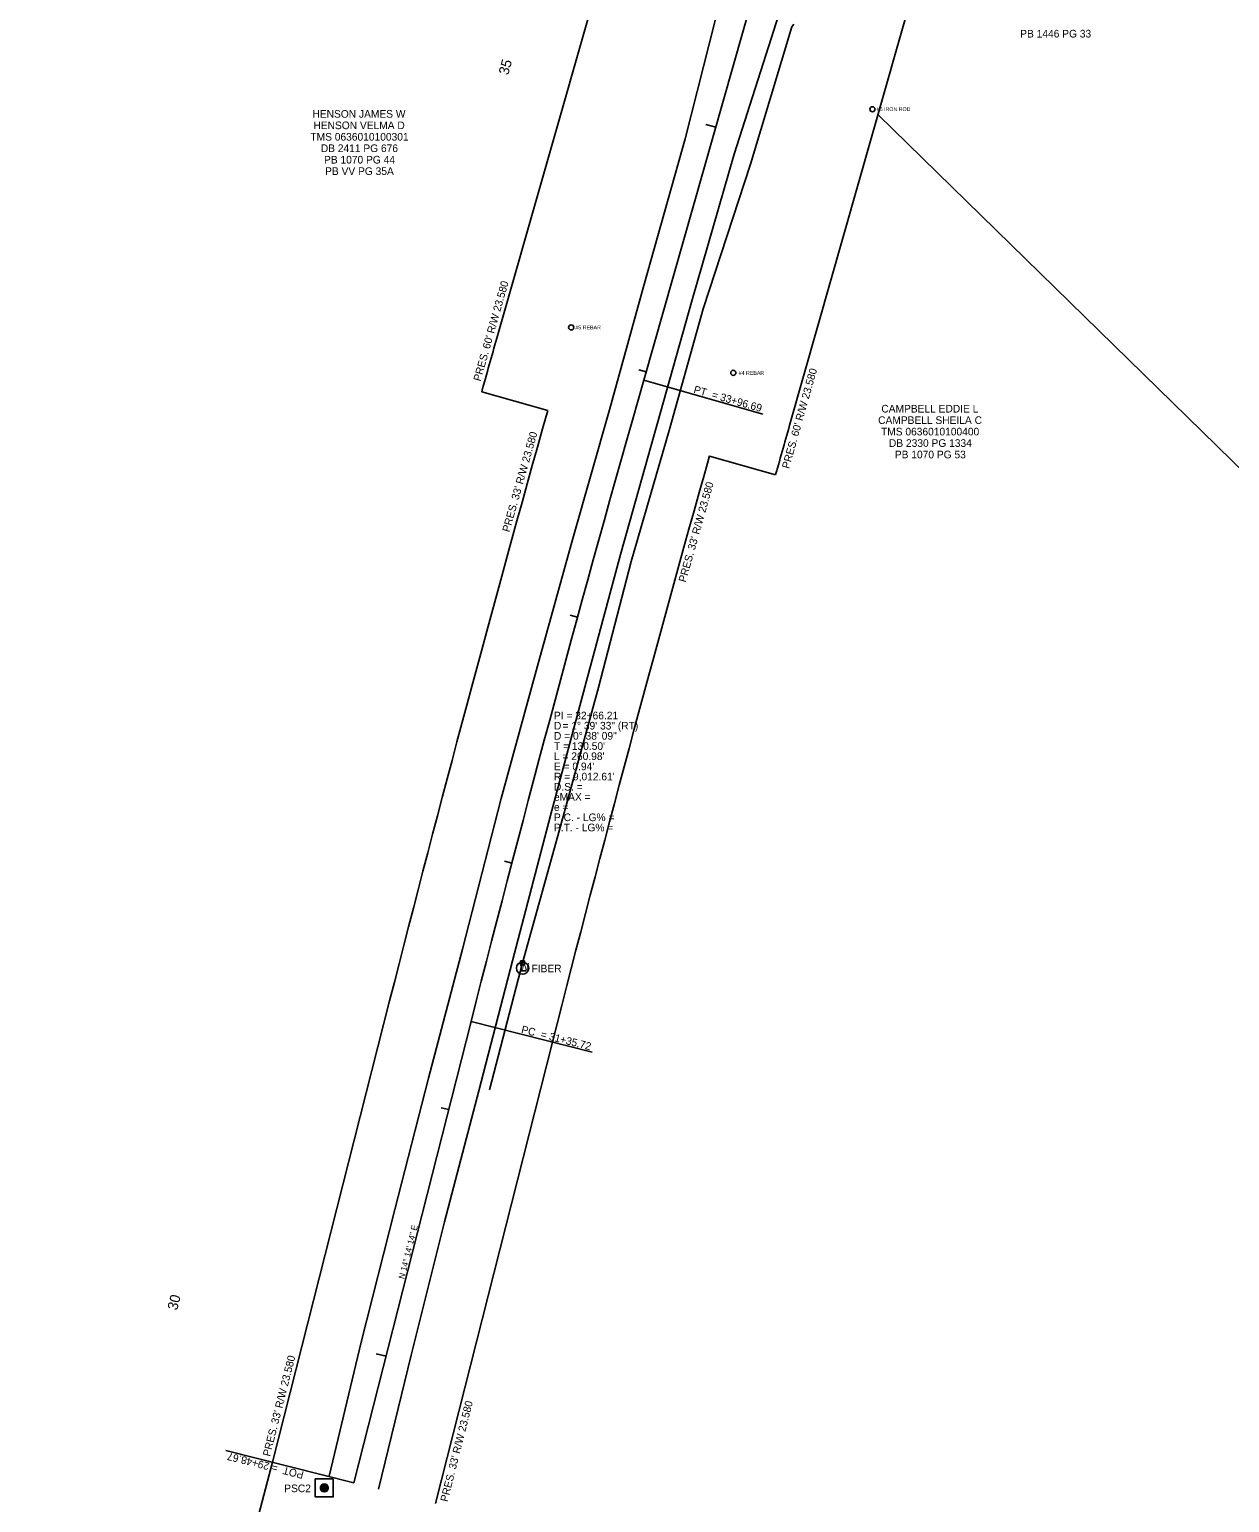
# Model space of a CAD drawing. Extents: x 1618707 to 1620612, y 1189955 to 1192629.
# Drawn here: x 1619369 to 1619840, y 1190966 to 1191545 of the extents above; entities that cross this region are included whole.
import ezdxf

# ---------------------------------------------------------------- set-up
doc = ezdxf.new("R2010")
doc.units = 0
for name, color, linetype in [('RD_EX_DV_Prop', 7, 'Continuous'), ('RD_EX_DV_Prop_txCode', 7, 'Continuous'), ('RD_EX_DV_PropPin', 7, 'Continuous'), ('RD_EX_DV_TX_Prop', 7, 'Continuous'), ('RD_EX_Road', 7, 'Continuous'), ('RD_EX_RW', 7, 'Continuous'), ('RD_EX_RW_TX', 7, 'Continuous'), ('RD_EX_SU_Telecom', 7, 'Continuous'), ('RD_EX_UT', 7, 'Continuous'), ('RD_HC_Cl', 7, 'Continuous'), ('RD_HC_Data', 7, 'Continuous'), ('RD_HC_Data_Tic', 7, 'Continuous'), ('RD_HC_Survey', 7, 'Continuous'), ('RD_HC_Survey_txCode', 7, 'Continuous'), ('RD_HC_TX_Sta20', 7, 'Continuous'), ('RD_TX_Utilities', 7, 'Continuous')]:
    doc.layers.add(name, color=color, linetype=linetype)

msp = doc.modelspace()

# ---------------------------------------------------------------- linework, layer by layer
at = {"layer": 'RD_EX_DV_Prop'}
for points in [[(1619702.33, 1191511.51), (1620061.32, 1191160.82), (1620043.47, 1191098.44), (1620079.72, 1190971.71), (1620114.14, 1190975.41), (1620199.12, 1190966.95), (1620233.68, 1190992.64), (1620266.69, 1190990.15), (1619987.51, 1189954.99)], [(1619464.43, 1190982.1), (1619428.11, 1190844.09), (1619368.9, 1190592.41)]]:
    msp.add_lwpolyline(points, dxfattribs=at)
at = {"layer": 'RD_EX_DV_PropPin'}
for centre in [(1619700.11, 1191513.68), (1619581.77, 1191427.98), (1619645.47, 1191410.14)]:
    msp.add_circle(centre, 1, dxfattribs=at)
at = {"layer": 'RD_EX_Road'}
for points in [[(1619642.43, 1191568.08), (1619638.48, 1191549.06), (1619626.5, 1191502.03), (1619610.31, 1191444.44), (1619596.77, 1191395.56), (1619582.42, 1191345.02), (1619568.38, 1191294.44), (1619554.25, 1191242.83), (1619539.08, 1191183.69), (1619525.7, 1191133.06), (1619512.41, 1191081.45), (1619499.3, 1191029.35), (1619486.66, 1190976.67)], [(1619666.44, 1191560.82), (1619645.74, 1191496.06), (1619629.32, 1191438.84), (1619615.59, 1191389.97), (1619601.08, 1191338.73), (1619587.7, 1191288.59), (1619573.66, 1191236.16), (1619558.66, 1191179.12), (1619545.49, 1191128.07), (1619532.02, 1191076.56), (1619518.85, 1191024.15), (1619506.08, 1190971.55)]]:
    msp.add_lwpolyline(points, dxfattribs=at)
at = {"layer": 'RD_EX_RW'}
for p, q in [((1619552.55, 1191423.72), (1619669.87, 1191835.65)), ((1619667.96, 1191390.85), (1619785.28, 1191802.78)), ((1619546.6, 1191402.71), (1619572.58, 1191395.38)), ((1619662.09, 1191370.12), (1619636.1, 1191377.45)), ((1619464.43, 1190982.1), (1619510.43, 1191163.4)), ((1619528.41, 1190965.87), (1619574.41, 1191147.17))]:
    msp.add_line(p, q, dxfattribs=at)
for radius, start, end in [(9072.61, 164.10357, 164.241474), (9045.61, 164.241474, 165.762665), (8952.61, 164.10357, 164.241474), (8979.61, 164.241474, 165.762665)]:
    msp.add_arc((1628278.21, 1188938.74), radius, start, end, dxfattribs=at)
at = {"layer": 'RD_EX_SU_Telecom'}
msp.add_lwpolyline([(1619669.31, 1191547.12), (1619668.4, 1191546.05), (1619652.22, 1191492.17), (1619633.62, 1191435.33), (1619620.26, 1191387.53), (1619605.32, 1191335.94), (1619592.44, 1191286.44), (1619577.21, 1191230.52), (1619562.58, 1191178.36), (1619549.6, 1191128.37)], dxfattribs=at)
at = {"layer": 'RD_EX_UT'}
msp.add_line((1619561.6, 1191175.16), (1619563.91, 1191175.16), dxfattribs=at)
msp.add_lwpolyline([(1619563.37, 1191177.59), (1619561.87, 1191177.59), (1619561.87, 1191179.09), (1619563.37, 1191179.09)], close=True, dxfattribs=at)
msp.add_circle((1619562.66, 1191176.26), 2.45, dxfattribs=at)
at = {"layer": 'RD_HC_Cl'}
for p, q in [((1619610.26, 1191407.28), (1619772.92, 1191978.46)), ((1619496.42, 1190973.99), (1619542.42, 1191155.29))]:
    msp.add_line(p, q, dxfattribs=at)
msp.add_arc((1628278.21, 1188938.74), 9012.61, 164.10357, 165.762665, dxfattribs=at)
at = {"layer": 'RD_HC_Data'}
for p, q in [((1619610.26, 1191407.28), (1619657.06, 1191393.95)), ((1619542.42, 1191155.29), (1619590, 1191143.22)), ((1619496.42, 1190973.99), (1619446.05, 1190986.77))]:
    msp.add_line(p, q, dxfattribs=at)
at = {"layer": 'RD_HC_Data_Tic'}
for p, q in [((1619638.55, 1191506.64), (1619634.71, 1191507.74)), ((1619611.16, 1191410.46), (1619608.28, 1191411.29)), ((1619584.27, 1191314.15), (1619581.38, 1191314.94)), ((1619558.45, 1191217.54), (1619555.55, 1191218.3)), ((1619533.64, 1191120.67), (1619530.73, 1191121.41)), ((1619509.04, 1191023.74), (1619505.17, 1191024.72))]:
    msp.add_line(p, q, dxfattribs=at)
at = {"layer": 'RD_HC_Survey'}
for p, q in [((1619483.25, 1190971.64), (1619483.25, 1190972.37)), ((1619483.3, 1190971.48), (1619483.3, 1190972.53)), ((1619483.35, 1190971.36), (1619483.35, 1190972.66)), ((1619483.4, 1190971.26), (1619483.4, 1190972.76)), ((1619483.45, 1190971.17), (1619483.45, 1190972.84)), ((1619483.5, 1190971.1), (1619483.5, 1190972.91)), ((1619483.55, 1190971.03), (1619483.55, 1190972.98)), ((1619483.6, 1190970.97), (1619483.6, 1190973.04)), ((1619483.65, 1190970.92), (1619483.65, 1190973.09)), ((1619483.7, 1190970.87), (1619483.7, 1190973.14)), ((1619483.75, 1190970.83), (1619483.75, 1190973.19)), ((1619483.8, 1190970.78), (1619483.8, 1190973.23)), ((1619483.85, 1190970.75), (1619483.85, 1190973.27)), ((1619483.9, 1190970.71), (1619483.9, 1190973.3)), ((1619483.95, 1190970.68), (1619483.95, 1190973.33)), ((1619484, 1190970.65), (1619484, 1190973.36)), ((1619484.05, 1190970.62), (1619484.05, 1190973.39)), ((1619484.1, 1190970.6), (1619484.1, 1190973.41)), ((1619484.15, 1190970.58), (1619484.15, 1190973.44)), ((1619484.2, 1190970.56), (1619484.2, 1190973.46)), ((1619484.25, 1190970.54), (1619484.25, 1190973.47)), ((1619484.3, 1190970.52), (1619484.3, 1190973.49)), ((1619484.35, 1190970.51), (1619484.35, 1190973.51)), ((1619484.4, 1190970.49), (1619484.4, 1190973.52)), ((1619484.45, 1190970.48), (1619484.45, 1190973.53)), ((1619484.5, 1190970.47), (1619484.5, 1190973.54)), ((1619484.55, 1190970.47), (1619484.55, 1190973.55)), ((1619484.6, 1190970.46), (1619484.6, 1190973.55)), ((1619484.65, 1190970.46), (1619484.65, 1190973.56)), ((1619484.7, 1190970.45), (1619484.7, 1190973.56)), ((1619484.75, 1190970.45), (1619484.75, 1190973.56)), ((1619484.8, 1190970.45), (1619484.8, 1190973.56)), ((1619484.85, 1190970.45), (1619484.85, 1190973.56)), ((1619484.9, 1190970.46), (1619484.9, 1190973.55)), ((1619484.95, 1190970.46), (1619484.95, 1190973.55)), ((1619485, 1190970.47), (1619485, 1190973.54)), ((1619485.05, 1190970.48), (1619485.05, 1190973.53)), ((1619485.1, 1190970.49), (1619485.1, 1190973.52)), ((1619485.15, 1190970.5), (1619485.15, 1190973.51)), ((1619485.2, 1190970.51), (1619485.2, 1190973.5)), ((1619485.25, 1190970.53), (1619485.25, 1190973.48)), ((1619485.3, 1190970.55), (1619485.3, 1190973.46)), ((1619485.35, 1190970.57), (1619485.35, 1190973.45)), ((1619485.4, 1190970.59), (1619485.4, 1190973.42)), ((1619485.45, 1190970.61), (1619485.45, 1190973.4)), ((1619485.5, 1190970.64), (1619485.5, 1190973.37)), ((1619485.55, 1190970.67), (1619485.55, 1190973.35)), ((1619485.6, 1190970.7), (1619485.6, 1190973.32)), ((1619485.65, 1190970.73), (1619485.65, 1190973.28)), ((1619485.7, 1190970.77), (1619485.7, 1190973.25)), ((1619485.75, 1190970.81), (1619485.75, 1190973.21)), ((1619485.8, 1190970.85), (1619485.8, 1190973.16)), ((1619485.85, 1190970.9), (1619485.85, 1190973.12)), ((1619485.9, 1190970.95), (1619485.9, 1190973.06)), ((1619485.95, 1190971), (1619485.95, 1190973.01)), ((1619486, 1190971.07), (1619486, 1190972.95)), ((1619486.05, 1190971.14), (1619486.05, 1190972.88)), ((1619486.1, 1190971.21), (1619486.1, 1190972.8)), ((1619486.15, 1190971.31), (1619486.15, 1190972.71)), ((1619486.2, 1190971.42), (1619486.2, 1190972.6)), ((1619486.25, 1190971.56), (1619486.25, 1190972.46)), ((1619486.3, 1190971.78), (1619486.3, 1190972.23))]:
    msp.add_line(p, q, dxfattribs=at)
msp.add_lwpolyline([(1619488.29, 1190975.54), (1619481.22, 1190975.54), (1619481.22, 1190968.47), (1619488.29, 1190968.47)], close=True, dxfattribs=at)
msp.add_circle((1619484.76, 1190972.01), 1.55, dxfattribs=at)

# ---------------------------------------------------------------- texts
at = {"layer": 'RD_EX_DV_Prop_txCode'}
for s, p in [('#6 IRON ROD', (1619701.82, 1191513)), ('#5 REBAR', (1619583.42, 1191427.22)), ('#4 REBAR', (1619647.58, 1191409.33))]:
    msp.add_text(s, height=1.5, dxfattribs=at).set_placement(p)
at = {"layer": 'RD_EX_DV_TX_Prop'}
for s, p in [('PB 1446 PG 33', (1619758.2, 1191541.88)), ('HENSON JAMES W', (1619480.1, 1191510.37)), ('HENSON VELMA D', (1619480.47, 1191505.87)), ('TMS 0636010100301', (1619479.3, 1191501.37)), ('DB 2411 PG 676', (1619483.38, 1191496.87)), ('PB 1070 PG 44', (1619484.65, 1191492.37)), ('PB VV PG 35A', (1619485.08, 1191487.87)), ('CAMPBELL EDDIE L', (1619703.63, 1191394.54)), ('CAMPBELL SHEILA C', (1619702.38, 1191390.04)), ('TMS 0636010100400', (1619703.5, 1191385.54)), ('DB 2330 PG 1334', (1619706.62, 1191381.04)), ('PB 1070 PG 53', (1619708.94, 1191376.54))]:
    msp.add_text(s, height=3, dxfattribs=at).set_placement(p)
at = {"layer": 'RD_EX_RW_TX'}
for s, rotation, p in [("PRES. 60' R/W 23.580", 74.21861, (1619546.14, 1191406.6)), ("PRES. 60' R/W 23.580", 74.21908, (1619667.37, 1191372.26)), ("PRES. 33' R/W 23.580", 74.26956, (1619557.49, 1191347.34)), ("PRES. 33' R/W 23.580", 74.27076, (1619626.75, 1191327.63)), ("PRES. 33' R/W 23.580", 75.76267, (1619463.42, 1190984.2)), ("PRES. 33' R/W 23.580", 75.76267, (1619533.17, 1190966.36))]:
    msp.add_text(s, height=3, rotation=rotation, dxfattribs=at).set_placement(p)
at = {"layer": 'RD_EX_UT'}
msp.add_text('W', height=3, dxfattribs=at).set_placement((1619561.43, 1191175.26))
msp.add_text('E', height=1, rotation=360, dxfattribs=at).set_placement((1619562.14, 1191177.86))
at = {"layer": 'RD_HC_Data'}
for s, height, rotation, p in [('PT  = 33+96.69', 3, 344.10357, (1619629.63, 1191402.29)), ('PC  = 31+35.72', 3, 345.76267, (1619561.93, 1191150.85)), ('N 14%%d 14\' 14" E', 2.4, 75.76267, (1619516.18, 1191053.91)), ('POT  = 29+48.67', 3, 165.76267, (1619476.91, 1190978.42))]:
    msp.add_text(s, height=height, rotation=rotation, dxfattribs=at).set_placement(p)
for s, p in [('PI = 32+66.21', (1619575, 1191274)), ('   = 1%%d 39\' 33" (RT)', (1619575, 1191270)), ('D', (1619575, 1191270)), ('D = 0%%d 38\' 09"', (1619575, 1191266)), ("T = 130.50'", (1619575, 1191262)), ("L = 260.98'", (1619575, 1191258)), ("E = 0.94'", (1619575, 1191254)), ("R = 9,012.61'", (1619575, 1191250)), ('eMAX = ', (1619575, 1191242)), ('D.S. = ', (1619575, 1191246)), ('e = ', (1619575, 1191238)), ('P.C. - LG% = ', (1619575, 1191234)), ('P.T. - LG% = ', (1619575, 1191230))]:
    msp.add_text(s, height=3, dxfattribs=at).set_placement(p)
at = {"layer": 'RD_HC_Survey_txCode'}
msp.add_text('PSC2', height=3, dxfattribs=at).set_placement((1619469.01, 1190970.35))
at = {"layer": 'RD_HC_TX_Sta20'}
for s, rotation, p in [('35', 74.10357, (1619556.98, 1191526.88)), ('30', 75.76267, (1619426.91, 1191041.59))]:
    msp.add_text(s, height=4, rotation=rotation, dxfattribs=at).set_placement(p)
at = {"layer": 'RD_TX_Utilities'}
msp.add_text('FIBER', height=3, dxfattribs=at).set_placement((1619566.18, 1191174.6))

doc.saveas('drawing.dxf')
